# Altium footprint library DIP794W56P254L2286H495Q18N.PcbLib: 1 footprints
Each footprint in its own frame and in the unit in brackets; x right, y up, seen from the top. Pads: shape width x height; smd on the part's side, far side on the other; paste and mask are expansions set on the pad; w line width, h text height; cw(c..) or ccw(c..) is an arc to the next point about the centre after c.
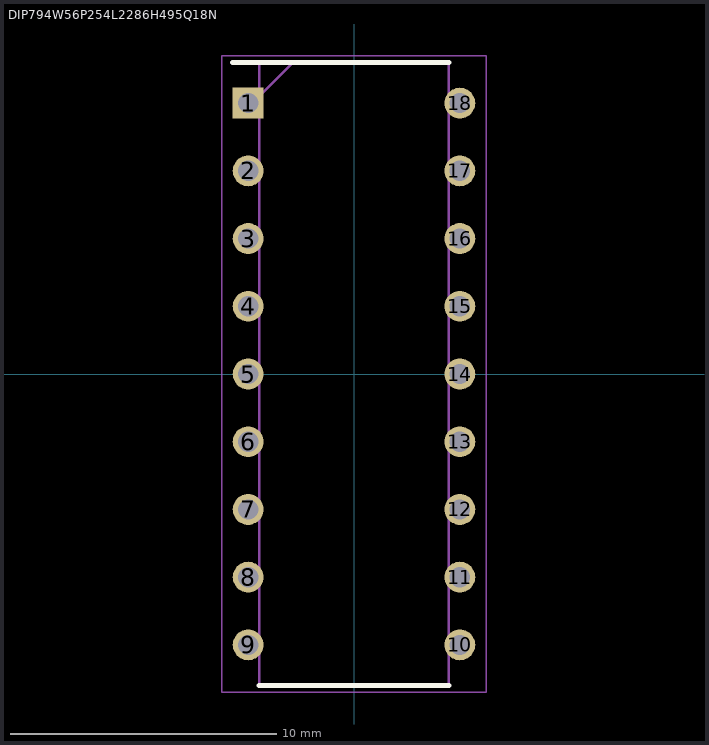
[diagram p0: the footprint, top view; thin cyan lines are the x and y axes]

## DIP794W56P254L2286H495Q18N [mil]
pads (18):
  rect 45.63x45.63 / inner round 45.63 / far side rect 45.63x45.63 hole 29.88: 1(-156.26,400)
  round 45.63 hole 29.88: 2(-156.26,300) 3(-156.26,200) 4(-156.26,100) 5(-156.26,0) 6(-156.26,-100) 7(-156.26,-200) 8(-156.26,-300) 9(-156.26,-400) 10(156.26,-400) 11(156.26,-300) 12(156.26,-200) 13(156.26,-100) 14(156.26,0) 15(156.26,100) 16(156.26,200) 17(156.26,300) 18(156.26,400)
Top Overlay:
  lines w7.87: -179.06,460 140,460 ; -140,-460 140,-460
Mechanical 15:
  lines w3.94: -140,410 -90,460 ; -140,-460 140,-460 140,460 -140,460 -140,-460
Mechanical 20:
  lines w1.97: -195.16,-469.84 195.16,-469.84 195.16,469.84 -195.16,469.84 -195.16,-469.84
